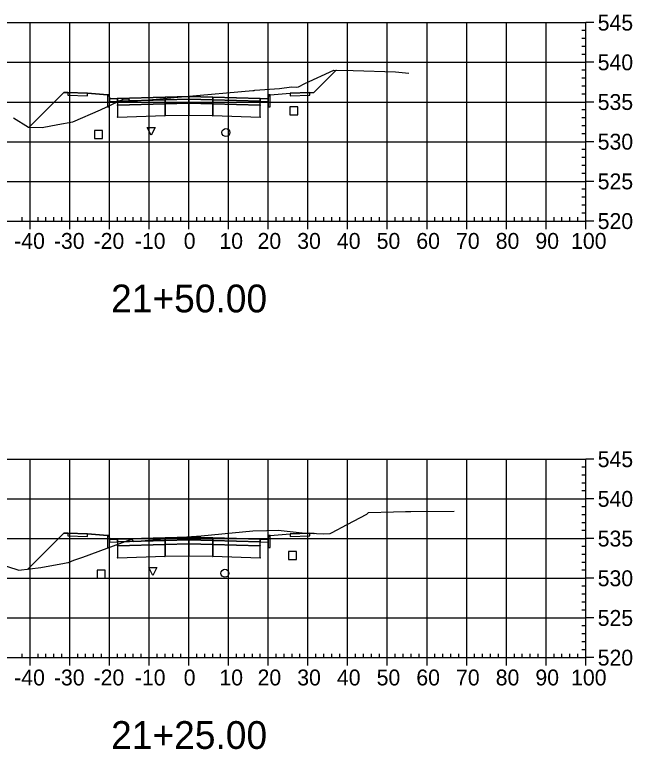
# Model space of a CAD drawing. Extents: x 704834 to 709892, y 372981 to 377533.
# Drawn here: x 707536 to 707691.6, y 376727.7 to 376912.8 of the extents above; entities that cross this region are included whole.
import ezdxf

# ---------------------------------------------------------------- set-up
doc = ezdxf.new("R2010")
doc.units = 0
for name, color, linetype in [('1', 7, 'Continuous'), ('10', 7, 'Continuous'), ('13', 7, 'Continuous'), ('14', 7, 'Continuous'), ('4', 7, 'Continuous'), ('57', 7, 'Continuous'), ('Default_Xsect', 7, 'Continuous'), ('Existing', 7, 'Continuous')]:
    doc.layers.add(name, color=color, linetype=linetype)

msp = doc.modelspace()

# ---------------------------------------------------------------- linework, layer by layer
for points in [[(707611.41, 376893.18), (707617.05, 376898.81)], [(707548.41, 376893.18), (707539.7, 376884.46)], [(707549.41, 376893.22), (707548.41, 376893.18)], [(707559.41, 376892.62), (707554.41, 376893.02)], [(707600.41, 376892.62), (707605.41, 376893.02)], [(707610.41, 376893.22), (707611.41, 376893.18)], [(707548.41, 376782.15), (707539.38, 376773.12)], [(707549.41, 376782.19), (707548.41, 376782.15)], [(707559.41, 376781.59), (707554.41, 376781.99)], [(707600.41, 376781.59), (707605.41, 376781.99)], [(707610.41, 376782.19), (707611.41, 376782.15)], [(707611.41, 376782.15), (707611.45, 376782.12)]]:
    msp.add_lwpolyline(points)
for points in [[(707554.41, 376893.02), (707549.41, 376893.22), (707549.41, 376892.55), (707554.41, 376892.35)], [(707559.91, 376891.62), (707559.83, 376892.62), (707559.41, 376892.62), (707559.41, 376889.62), (707559.91, 376889.62)], [(707573.91, 376892.06), (707561.91, 376891.7), (707561.91, 376891.03), (707573.91, 376891.39)], [(707579.91, 376892.18), (707573.91, 376892.06), (707573.91, 376891.39), (707579.91, 376891.51)], [(707579.91, 376891.51), (707585.91, 376891.39), (707585.91, 376892.06), (707579.91, 376892.18)], [(707585.91, 376891.39), (707597.91, 376891.03), (707597.91, 376891.7), (707585.91, 376892.06)], [(707599.91, 376889.62), (707600.41, 376889.62), (707600.41, 376892.62), (707600, 376892.62), (707599.91, 376891.62)], [(707605.41, 376892.35), (707610.41, 376892.55), (707610.41, 376893.22), (707605.41, 376893.02)], [(707561.91, 376891.7), (707559.91, 376891.62), (707559.91, 376890.95), (707561.91, 376891.03)], [(707561.86, 376889.98), (707561.96, 376889.98), (707561.96, 376890.08), (707561.86, 376890.08)], [(707573.91, 376891.39), (707561.91, 376891.03), (707561.91, 376890.03), (707573.91, 376890.39)], [(707573.91, 376890.39), (707561.91, 376890.03), (707561.91, 376887.03), (707573.91, 376887.39)], [(707573.86, 376891.34), (707573.96, 376891.34), (707573.96, 376891.44), (707573.86, 376891.44)], [(707573.86, 376890.34), (707573.96, 376890.34), (707573.96, 376890.44), (707573.86, 376890.44)], [(707579.91, 376891.51), (707573.91, 376891.39), (707573.91, 376890.39), (707579.91, 376890.51)], [(707579.91, 376890.51), (707573.91, 376890.39), (707573.91, 376887.39), (707579.91, 376887.51)], [(707579.86, 376891.46), (707579.96, 376891.46), (707579.96, 376891.56), (707579.86, 376891.56)], [(707579.86, 376890.46), (707579.96, 376890.46), (707579.96, 376890.56), (707579.86, 376890.56)], [(707579.91, 376890.51), (707585.91, 376890.39), (707585.91, 376891.39), (707579.91, 376891.51)], [(707579.91, 376887.51), (707585.91, 376887.39), (707585.91, 376890.39), (707579.91, 376890.51)], [(707585.86, 376891.34), (707585.96, 376891.34), (707585.96, 376891.44), (707585.86, 376891.44)], [(707585.86, 376890.34), (707585.96, 376890.34), (707585.96, 376890.44), (707585.86, 376890.44)], [(707585.91, 376890.39), (707597.91, 376890.03), (707597.91, 376891.03), (707585.91, 376891.39)], [(707585.91, 376887.39), (707597.91, 376887.03), (707597.91, 376890.03), (707585.91, 376890.39)], [(707597.86, 376889.98), (707597.96, 376889.98), (707597.96, 376890.08), (707597.86, 376890.08)], [(707597.91, 376891.03), (707599.91, 376890.95), (707599.91, 376891.62), (707597.91, 376891.7)], [(707561.86, 376886.98), (707561.96, 376886.98), (707561.96, 376887.08), (707561.86, 376887.08)], [(707573.86, 376887.34), (707573.96, 376887.34), (707573.96, 376887.44), (707573.86, 376887.44)], [(707579.86, 376887.46), (707579.96, 376887.46), (707579.96, 376887.56), (707579.86, 376887.56)], [(707585.86, 376887.34), (707585.96, 376887.34), (707585.96, 376887.44), (707585.86, 376887.44)], [(707597.86, 376886.98), (707597.96, 376886.98), (707597.96, 376887.08), (707597.86, 376887.08)], [(707554.41, 376781.99), (707549.41, 376782.19), (707549.41, 376781.53), (707554.41, 376781.33)], [(707559.91, 376780.59), (707559.83, 376781.59), (707559.41, 376781.59), (707559.41, 376778.59), (707559.91, 376778.59)], [(707573.91, 376781.03), (707561.91, 376780.67), (707561.91, 376780.01), (707573.91, 376780.37)], [(707579.91, 376781.15), (707573.91, 376781.03), (707573.91, 376780.37), (707579.91, 376780.49)], [(707579.91, 376780.49), (707585.91, 376780.37), (707585.91, 376781.03), (707579.91, 376781.15)], [(707585.91, 376780.37), (707597.91, 376780.01), (707597.91, 376780.67), (707585.91, 376781.03)], [(707599.91, 376778.59), (707600.41, 376778.59), (707600.41, 376781.59), (707600, 376781.59), (707599.91, 376780.59)], [(707605.41, 376781.33), (707610.41, 376781.53), (707610.41, 376782.19), (707605.41, 376781.99)], [(707561.91, 376780.67), (707559.91, 376780.59), (707559.91, 376779.93), (707561.91, 376780.01)], [(707561.86, 376778.96), (707561.96, 376778.96), (707561.96, 376779.06), (707561.86, 376779.06)], [(707573.91, 376780.37), (707561.91, 376780.01), (707561.91, 376779.01), (707573.91, 376779.37)], [(707573.91, 376779.37), (707561.91, 376779.01), (707561.91, 376776.01), (707573.91, 376776.37)], [(707573.86, 376780.32), (707573.96, 376780.32), (707573.96, 376780.42), (707573.86, 376780.42)], [(707573.86, 376779.32), (707573.96, 376779.32), (707573.96, 376779.42), (707573.86, 376779.42)], [(707579.91, 376780.49), (707573.91, 376780.37), (707573.91, 376779.37), (707579.91, 376779.49)], [(707579.91, 376779.49), (707573.91, 376779.37), (707573.91, 376776.37), (707579.91, 376776.49)], [(707579.86, 376780.44), (707579.96, 376780.44), (707579.96, 376780.54), (707579.86, 376780.54)], [(707579.86, 376779.44), (707579.96, 376779.44), (707579.96, 376779.54), (707579.86, 376779.54)], [(707579.91, 376779.49), (707585.91, 376779.37), (707585.91, 376780.37), (707579.91, 376780.49)], [(707579.91, 376776.49), (707585.91, 376776.37), (707585.91, 376779.37), (707579.91, 376779.49)], [(707585.86, 376780.32), (707585.96, 376780.32), (707585.96, 376780.42), (707585.86, 376780.42)], [(707585.86, 376779.32), (707585.96, 376779.32), (707585.96, 376779.42), (707585.86, 376779.42)], [(707585.91, 376779.37), (707597.91, 376779.01), (707597.91, 376780.01), (707585.91, 376780.37)], [(707585.91, 376776.37), (707597.91, 376776.01), (707597.91, 376779.01), (707585.91, 376779.37)], [(707597.86, 376778.96), (707597.96, 376778.96), (707597.96, 376779.06), (707597.86, 376779.06)], [(707597.91, 376780.01), (707599.91, 376779.93), (707599.91, 376780.59), (707597.91, 376780.67)], [(707561.86, 376775.96), (707561.96, 376775.96), (707561.96, 376776.06), (707561.86, 376776.06)], [(707573.86, 376776.32), (707573.96, 376776.32), (707573.96, 376776.42), (707573.86, 376776.42)], [(707579.86, 376776.44), (707579.96, 376776.44), (707579.96, 376776.54), (707579.86, 376776.54)], [(707585.86, 376776.32), (707585.96, 376776.32), (707585.96, 376776.42), (707585.86, 376776.42)], [(707597.86, 376775.96), (707597.96, 376775.96), (707597.96, 376776.06), (707597.86, 376776.06)]]:
    msp.add_lwpolyline(points, close=True)
at = {"layer": '1'}
for points in [[(707570.44, 376882.44), (707569.44, 376884.44), (707571.44, 376884.44)], [(707570.82, 376771.53), (707569.82, 376773.53), (707571.82, 376773.53)]]:
    msp.add_lwpolyline(points, close=True, dxfattribs=at)
at = {"layer": '10'}
for points in [[(707556.18, 376881.61), (707558.18, 376881.61), (707558.18, 376883.61), (707556.18, 376883.61)], [(707556.85, 376770.87), (707558.85, 376770.87), (707558.85, 376772.87), (707556.85, 376772.87)]]:
    msp.add_lwpolyline(points, close=True, dxfattribs=at)
at = {"layer": '13'}
for centre in [(707589.24, 376883.13), (707589, 376772.09)]:
    msp.add_circle(centre, 1, dxfattribs=at)
at = {"layer": '14'}
for points in [[(707617.05, 376898.81), (707617.05, 376898.86), (707617.05, 376898.81), (707617, 376898.81), (707617.05, 376898.81), (707617.05, 376898.76), (707617.05, 376898.81), (707617.1, 376898.81)], [(707579.91, 376892.18), (707579.91, 376892.23), (707579.91, 376892.18), (707579.86, 376892.18), (707579.91, 376892.18), (707579.91, 376892.13), (707579.91, 376892.18), (707579.96, 376892.18)], [(707561.91, 376891.7), (707561.91, 376891.75), (707561.91, 376891.7), (707561.86, 376891.7), (707561.91, 376891.7), (707561.91, 376891.65), (707561.91, 376891.7), (707561.96, 376891.7)], [(707597.91, 376891.7), (707597.91, 376891.75), (707597.91, 376891.7), (707597.86, 376891.7), (707597.91, 376891.7), (707597.91, 376891.65), (707597.91, 376891.7), (707597.96, 376891.7)], [(707539.7, 376884.46), (707539.7, 376884.51), (707539.7, 376884.46), (707539.65, 376884.46), (707539.7, 376884.46), (707539.7, 376884.41), (707539.7, 376884.46), (707539.75, 376884.46)], [(707579.91, 376781.15), (707579.91, 376781.2), (707579.91, 376781.15), (707579.86, 376781.15), (707579.91, 376781.15), (707579.91, 376781.1), (707579.91, 376781.15), (707579.96, 376781.15)], [(707611.45, 376782.12), (707611.45, 376782.17), (707611.45, 376782.12), (707611.4, 376782.12), (707611.45, 376782.12), (707611.45, 376782.07), (707611.45, 376782.12), (707611.5, 376782.12)], [(707611.45, 376782.12), (707611.45, 376782.17), (707611.45, 376782.12), (707611.4, 376782.12), (707611.45, 376782.12), (707611.45, 376782.07), (707611.45, 376782.12), (707611.5, 376782.12)], [(707561.91, 376780.67), (707561.91, 376780.72), (707561.91, 376780.67), (707561.86, 376780.67), (707561.91, 376780.67), (707561.91, 376780.62), (707561.91, 376780.67), (707561.96, 376780.67)], [(707597.91, 376780.67), (707597.91, 376780.72), (707597.91, 376780.67), (707597.86, 376780.67), (707597.91, 376780.67), (707597.91, 376780.62), (707597.91, 376780.67), (707597.96, 376780.67)], [(707539.38, 376773.12), (707539.38, 376773.17), (707539.38, 376773.12), (707539.33, 376773.12), (707539.38, 376773.12), (707539.38, 376773.07), (707539.38, 376773.12), (707539.43, 376773.12)]]:
    msp.add_lwpolyline(points, dxfattribs=at)
at = {"layer": '4'}
for points in [[(707605.36, 376887.59), (707607.36, 376887.59), (707607.36, 376889.59), (707605.36, 376889.59)], [(707605.01, 376775.57), (707607.01, 376775.57), (707607.01, 376777.57), (707605.01, 376777.57)]]:
    msp.add_lwpolyline(points, close=True, dxfattribs=at)
at = {"layer": '57'}
for p, q in [((707479.91, 376910.82), (707679.91, 376910.82)), ((707539.91, 376860.82), (707539.91, 376910.82)), ((707549.91, 376860.82), (707549.91, 376910.82)), ((707559.91, 376860.82), (707559.91, 376910.82)), ((707569.91, 376860.82), (707569.91, 376910.82)), ((707579.91, 376860.82), (707579.91, 376910.82)), ((707589.91, 376860.82), (707589.91, 376910.82)), ((707599.91, 376860.82), (707599.91, 376910.82)), ((707609.91, 376860.82), (707609.91, 376910.82)), ((707619.91, 376860.82), (707619.91, 376910.82)), ((707629.91, 376860.82), (707629.91, 376910.82)), ((707639.91, 376860.82), (707639.91, 376910.82)), ((707649.91, 376860.82), (707649.91, 376910.82)), ((707659.91, 376860.82), (707659.91, 376910.82)), ((707669.91, 376860.82), (707669.91, 376910.82)), ((707679.91, 376860.82), (707679.91, 376910.82)), ((707679.91, 376860.82), (707679.91, 376910.82)), ((707681.91, 376910.82), (707679.91, 376910.82)), ((707679.91, 376908.82), (707678.91, 376908.82)), ((707679.91, 376906.82), (707678.91, 376906.82)), ((707679.91, 376904.82), (707678.91, 376904.82)), ((707679.91, 376902.82), (707678.91, 376902.82)), ((707479.91, 376900.82), (707679.91, 376900.82)), ((707681.91, 376900.82), (707679.91, 376900.82)), ((707679.91, 376898.82), (707678.91, 376898.82)), ((707679.91, 376896.82), (707678.91, 376896.82)), ((707679.91, 376894.82), (707678.91, 376894.82)), ((707679.91, 376892.82), (707678.91, 376892.82)), ((707479.91, 376890.82), (707679.91, 376890.82)), ((707681.91, 376890.82), (707679.91, 376890.82)), ((707679.91, 376888.82), (707678.91, 376888.82)), ((707679.91, 376886.82), (707678.91, 376886.82)), ((707679.91, 376884.82), (707678.91, 376884.82)), ((707679.91, 376882.82), (707678.91, 376882.82)), ((707479.91, 376880.82), (707679.91, 376880.82)), ((707681.91, 376880.82), (707679.91, 376880.82)), ((707679.91, 376878.82), (707678.91, 376878.82)), ((707679.91, 376876.82), (707678.91, 376876.82)), ((707679.91, 376874.82), (707678.91, 376874.82)), ((707679.91, 376872.82), (707678.91, 376872.82)), ((707479.91, 376870.82), (707679.91, 376870.82)), ((707681.91, 376870.82), (707679.91, 376870.82)), ((707679.91, 376868.82), (707678.91, 376868.82)), ((707679.91, 376866.82), (707678.91, 376866.82)), ((707679.91, 376864.82), (707678.91, 376864.82)), ((707679.91, 376862.82), (707678.91, 376862.82)), ((707479.91, 376860.82), (707679.91, 376860.82)), ((707479.91, 376860.82), (707679.91, 376860.82)), ((707537.91, 376860.82), (707537.91, 376861.82)), ((707539.91, 376858.82), (707539.91, 376860.82)), ((707541.91, 376860.82), (707541.91, 376861.82)), ((707543.91, 376860.82), (707543.91, 376861.82)), ((707545.91, 376860.82), (707545.91, 376861.82)), ((707547.91, 376860.82), (707547.91, 376861.82)), ((707549.91, 376858.82), (707549.91, 376860.82)), ((707551.91, 376860.82), (707551.91, 376861.82)), ((707553.91, 376860.82), (707553.91, 376861.82)), ((707555.91, 376860.82), (707555.91, 376861.82)), ((707557.91, 376860.82), (707557.91, 376861.82)), ((707559.91, 376858.82), (707559.91, 376860.82)), ((707561.91, 376860.82), (707561.91, 376861.82)), ((707563.91, 376860.82), (707563.91, 376861.82)), ((707565.91, 376860.82), (707565.91, 376861.82)), ((707567.91, 376860.82), (707567.91, 376861.82)), ((707569.91, 376858.82), (707569.91, 376860.82)), ((707571.91, 376860.82), (707571.91, 376861.82)), ((707573.91, 376860.82), (707573.91, 376861.82)), ((707575.91, 376860.82), (707575.91, 376861.82)), ((707577.91, 376860.82), (707577.91, 376861.82)), ((707579.91, 376858.82), (707579.91, 376860.82)), ((707581.91, 376860.82), (707581.91, 376861.82)), ((707583.91, 376860.82), (707583.91, 376861.82)), ((707585.91, 376860.82), (707585.91, 376861.82)), ((707587.91, 376860.82), (707587.91, 376861.82)), ((707589.91, 376858.82), (707589.91, 376860.82)), ((707591.91, 376860.82), (707591.91, 376861.82)), ((707593.91, 376860.82), (707593.91, 376861.82)), ((707595.91, 376860.82), (707595.91, 376861.82)), ((707597.91, 376860.82), (707597.91, 376861.82)), ((707599.91, 376858.82), (707599.91, 376860.82)), ((707601.91, 376860.82), (707601.91, 376861.82)), ((707603.91, 376860.82), (707603.91, 376861.82)), ((707605.91, 376860.82), (707605.91, 376861.82)), ((707607.91, 376860.82), (707607.91, 376861.82)), ((707609.91, 376858.82), (707609.91, 376860.82)), ((707611.91, 376860.82), (707611.91, 376861.82)), ((707613.91, 376860.82), (707613.91, 376861.82)), ((707615.91, 376860.82), (707615.91, 376861.82)), ((707617.91, 376860.82), (707617.91, 376861.82)), ((707619.91, 376858.82), (707619.91, 376860.82)), ((707621.91, 376860.82), (707621.91, 376861.82)), ((707623.91, 376860.82), (707623.91, 376861.82)), ((707625.91, 376860.82), (707625.91, 376861.82)), ((707627.91, 376860.82), (707627.91, 376861.82)), ((707629.91, 376858.82), (707629.91, 376860.82)), ((707631.91, 376860.82), (707631.91, 376861.82)), ((707633.91, 376860.82), (707633.91, 376861.82)), ((707635.91, 376860.82), (707635.91, 376861.82)), ((707637.91, 376860.82), (707637.91, 376861.82)), ((707639.91, 376858.82), (707639.91, 376860.82)), ((707641.91, 376860.82), (707641.91, 376861.82)), ((707643.91, 376860.82), (707643.91, 376861.82)), ((707645.91, 376860.82), (707645.91, 376861.82)), ((707647.91, 376860.82), (707647.91, 376861.82)), ((707649.91, 376858.82), (707649.91, 376860.82)), ((707651.91, 376860.82), (707651.91, 376861.82)), ((707653.91, 376860.82), (707653.91, 376861.82)), ((707655.91, 376860.82), (707655.91, 376861.82)), ((707657.91, 376860.82), (707657.91, 376861.82)), ((707659.91, 376858.82), (707659.91, 376860.82)), ((707661.91, 376860.82), (707661.91, 376861.82)), ((707663.91, 376860.82), (707663.91, 376861.82)), ((707665.91, 376860.82), (707665.91, 376861.82)), ((707667.91, 376860.82), (707667.91, 376861.82)), ((707669.91, 376858.82), (707669.91, 376860.82)), ((707671.91, 376860.82), (707671.91, 376861.82)), ((707673.91, 376860.82), (707673.91, 376861.82)), ((707675.91, 376860.82), (707675.91, 376861.82)), ((707677.91, 376860.82), (707677.91, 376861.82)), ((707679.91, 376858.82), (707679.91, 376860.82)), ((707681.91, 376860.82), (707679.91, 376860.82)), ((707479.91, 376800.82), (707679.91, 376800.82)), ((707539.91, 376750.82), (707539.91, 376800.82)), ((707549.91, 376750.82), (707549.91, 376800.82)), ((707559.91, 376750.82), (707559.91, 376800.82)), ((707569.91, 376750.82), (707569.91, 376800.82)), ((707579.91, 376750.82), (707579.91, 376800.82)), ((707589.91, 376750.82), (707589.91, 376800.82)), ((707599.91, 376750.82), (707599.91, 376800.82)), ((707609.91, 376750.82), (707609.91, 376800.82)), ((707619.91, 376750.82), (707619.91, 376800.82)), ((707629.91, 376750.82), (707629.91, 376800.82)), ((707639.91, 376750.82), (707639.91, 376800.82)), ((707649.91, 376750.82), (707649.91, 376800.82)), ((707659.91, 376750.82), (707659.91, 376800.82)), ((707669.91, 376750.82), (707669.91, 376800.82)), ((707679.91, 376750.82), (707679.91, 376800.82)), ((707679.91, 376750.82), (707679.91, 376800.82)), ((707681.91, 376800.82), (707679.91, 376800.82)), ((707679.91, 376798.82), (707678.91, 376798.82)), ((707679.91, 376796.82), (707678.91, 376796.82)), ((707679.91, 376794.82), (707678.91, 376794.82)), ((707679.91, 376792.82), (707678.91, 376792.82)), ((707479.91, 376790.82), (707679.91, 376790.82)), ((707681.91, 376790.82), (707679.91, 376790.82)), ((707679.91, 376788.82), (707678.91, 376788.82)), ((707679.91, 376786.82), (707678.91, 376786.82)), ((707679.91, 376784.82), (707678.91, 376784.82)), ((707679.91, 376782.82), (707678.91, 376782.82)), ((707479.91, 376780.82), (707679.91, 376780.82)), ((707681.91, 376780.82), (707679.91, 376780.82)), ((707679.91, 376778.82), (707678.91, 376778.82)), ((707679.91, 376776.82), (707678.91, 376776.82)), ((707679.91, 376774.82), (707678.91, 376774.82)), ((707679.91, 376772.82), (707678.91, 376772.82)), ((707479.91, 376770.82), (707679.91, 376770.82)), ((707681.91, 376770.82), (707679.91, 376770.82)), ((707679.91, 376768.82), (707678.91, 376768.82)), ((707679.91, 376766.82), (707678.91, 376766.82)), ((707679.91, 376764.82), (707678.91, 376764.82)), ((707679.91, 376762.82), (707678.91, 376762.82)), ((707479.91, 376760.82), (707679.91, 376760.82)), ((707681.91, 376760.82), (707679.91, 376760.82)), ((707679.91, 376758.82), (707678.91, 376758.82)), ((707679.91, 376756.82), (707678.91, 376756.82)), ((707679.91, 376754.82), (707678.91, 376754.82)), ((707537.91, 376750.82), (707537.91, 376751.82)), ((707541.91, 376750.82), (707541.91, 376751.82)), ((707543.91, 376750.82), (707543.91, 376751.82)), ((707545.91, 376750.82), (707545.91, 376751.82)), ((707547.91, 376750.82), (707547.91, 376751.82)), ((707551.91, 376750.82), (707551.91, 376751.82)), ((707553.91, 376750.82), (707553.91, 376751.82)), ((707555.91, 376750.82), (707555.91, 376751.82)), ((707557.91, 376750.82), (707557.91, 376751.82)), ((707561.91, 376750.82), (707561.91, 376751.82)), ((707563.91, 376750.82), (707563.91, 376751.82)), ((707565.91, 376750.82), (707565.91, 376751.82)), ((707567.91, 376750.82), (707567.91, 376751.82)), ((707571.91, 376750.82), (707571.91, 376751.82)), ((707573.91, 376750.82), (707573.91, 376751.82)), ((707575.91, 376750.82), (707575.91, 376751.82)), ((707577.91, 376750.82), (707577.91, 376751.82)), ((707581.91, 376750.82), (707581.91, 376751.82)), ((707583.91, 376750.82), (707583.91, 376751.82)), ((707585.91, 376750.82), (707585.91, 376751.82)), ((707587.91, 376750.82), (707587.91, 376751.82)), ((707591.91, 376750.82), (707591.91, 376751.82)), ((707593.91, 376750.82), (707593.91, 376751.82)), ((707595.91, 376750.82), (707595.91, 376751.82)), ((707597.91, 376750.82), (707597.91, 376751.82)), ((707601.91, 376750.82), (707601.91, 376751.82)), ((707603.91, 376750.82), (707603.91, 376751.82)), ((707605.91, 376750.82), (707605.91, 376751.82)), ((707607.91, 376750.82), (707607.91, 376751.82)), ((707611.91, 376750.82), (707611.91, 376751.82)), ((707613.91, 376750.82), (707613.91, 376751.82)), ((707615.91, 376750.82), (707615.91, 376751.82)), ((707617.91, 376750.82), (707617.91, 376751.82)), ((707621.91, 376750.82), (707621.91, 376751.82)), ((707623.91, 376750.82), (707623.91, 376751.82)), ((707625.91, 376750.82), (707625.91, 376751.82)), ((707627.91, 376750.82), (707627.91, 376751.82)), ((707631.91, 376750.82), (707631.91, 376751.82)), ((707633.91, 376750.82), (707633.91, 376751.82)), ((707635.91, 376750.82), (707635.91, 376751.82)), ((707637.91, 376750.82), (707637.91, 376751.82)), ((707641.91, 376750.82), (707641.91, 376751.82)), ((707643.91, 376750.82), (707643.91, 376751.82)), ((707645.91, 376750.82), (707645.91, 376751.82)), ((707647.91, 376750.82), (707647.91, 376751.82)), ((707651.91, 376750.82), (707651.91, 376751.82)), ((707653.91, 376750.82), (707653.91, 376751.82)), ((707655.91, 376750.82), (707655.91, 376751.82)), ((707657.91, 376750.82), (707657.91, 376751.82)), ((707661.91, 376750.82), (707661.91, 376751.82)), ((707663.91, 376750.82), (707663.91, 376751.82)), ((707665.91, 376750.82), (707665.91, 376751.82)), ((707667.91, 376750.82), (707667.91, 376751.82)), ((707671.91, 376750.82), (707671.91, 376751.82)), ((707673.91, 376750.82), (707673.91, 376751.82)), ((707675.91, 376750.82), (707675.91, 376751.82)), ((707677.91, 376750.82), (707677.91, 376751.82)), ((707679.91, 376752.82), (707678.91, 376752.82)), ((707479.91, 376750.82), (707679.91, 376750.82)), ((707479.91, 376750.82), (707679.91, 376750.82)), ((707539.91, 376748.82), (707539.91, 376750.82)), ((707549.91, 376748.82), (707549.91, 376750.82)), ((707559.91, 376748.82), (707559.91, 376750.82)), ((707569.91, 376748.82), (707569.91, 376750.82)), ((707579.91, 376748.82), (707579.91, 376750.82)), ((707589.91, 376748.82), (707589.91, 376750.82)), ((707599.91, 376748.82), (707599.91, 376750.82)), ((707609.91, 376748.82), (707609.91, 376750.82)), ((707619.91, 376748.82), (707619.91, 376750.82)), ((707629.91, 376748.82), (707629.91, 376750.82)), ((707639.91, 376748.82), (707639.91, 376750.82)), ((707649.91, 376748.82), (707649.91, 376750.82)), ((707659.91, 376748.82), (707659.91, 376750.82)), ((707669.91, 376748.82), (707669.91, 376750.82)), ((707679.91, 376748.82), (707679.91, 376750.82)), ((707681.91, 376750.82), (707679.91, 376750.82))]:
    msp.add_line(p, q, dxfattribs=at)
at = {"layer": 'Default_Xsect'}
for points in [[(707539.7, 376884.46), (707548.41, 376893.18), (707549.41, 376893.22), (707554.41, 376893.02), (707559.41, 376892.62), (707559.83, 376892.62), (707559.91, 376891.62), (707561.91, 376891.7), (707573.91, 376892.06), (707579.91, 376892.18), (707585.91, 376892.06), (707597.91, 376891.7), (707599.91, 376891.62), (707600, 376892.62), (707600.41, 376892.62), (707605.41, 376893.02), (707610.41, 376893.22), (707611.41, 376893.18), (707617.05, 376898.81)], [(707539.38, 376773.12), (707548.41, 376782.15), (707549.41, 376782.19), (707554.41, 376781.99), (707559.41, 376781.59), (707559.83, 376781.59), (707559.91, 376780.59), (707561.91, 376780.67), (707573.91, 376781.03), (707579.91, 376781.15), (707585.91, 376781.03), (707597.91, 376780.67), (707599.91, 376780.59), (707600, 376781.59), (707600.41, 376781.59), (707605.41, 376781.99), (707610.41, 376782.19), (707611.41, 376782.15), (707611.45, 376782.12)]]:
    msp.add_lwpolyline(points, dxfattribs=at)
at = {"layer": 'Existing'}
for points in [[(707535.71, 376886.81), (707539.55, 376884.46), (707542.93, 376884.44), (707546.86, 376885.14), (707550.68, 376885.8), (707557.68, 376888.82), (707563.5, 376891.6), (707564.66, 376891.58), (707564.97, 376891.22), (707565.12, 376890.98), (707573.51, 376891.7), (707578.95, 376892.25), (707596.02, 376893.71), (707596.36, 376893.74), (707596.52, 376893.77), (707602.74, 376894.22), (707605.78, 376894.61), (707607.03, 376894.57), (707607.54, 376894.61), (707609.14, 376895.47), (707616.4, 376898.82), (707621.31, 376898.75), (707631.95, 376898.42), (707635.32, 376898.11)], [(707531.28, 376774.74), (707537.05, 376772.85), (707542.63, 376773.5), (707548.62, 376774.66), (707549.42, 376774.8), (707549.59, 376774.83), (707550.93, 376775.4), (707553.17, 376776.15), (707565.46, 376780.67), (707565.51, 376780.62), (707565.94, 376780.12), (707577.66, 376781.11), (707579.42, 376781.27), (707583.03, 376781.55), (707596.04, 376782.74), (707599.52, 376782.89), (707602.43, 376782.98), (707608.48, 376782.29), (707613.79, 376781.99), (707615.55, 376782.09), (707617.57, 376783.16), (707618.18, 376783.49), (707624.76, 376787.01), (707625.14, 376787.37), (707631.44, 376787.58), (707634.53, 376787.64), (707635.8, 376787.63), (707646.77, 376787.73)]]:
    msp.add_lwpolyline(points, dxfattribs=at)

# ---------------------------------------------------------------- texts
at = {"layer": '1'}
for s, p in [('21+50.00', (707560.32, 376837.82)), ('21+25.00', (707560.32, 376727.82))]:
    msp.add_text(s, height=7, dxfattribs=at).set_placement(p)
at = {"layer": '14'}
for p in [(707549.38, 376893.17), (707549.38, 376892.5), (707554.38, 376892.3), (707605.38, 376892.3), (707610.38, 376893.17), (707610.38, 376892.5), (707549.38, 376782.14), (707549.38, 376781.48), (707554.38, 376781.28), (707605.38, 376781.28), (707610.38, 376782.14), (707610.38, 376781.48)]:
    msp.add_text('+', height=0.1, dxfattribs=at).set_placement(p)
at = {"layer": '57'}
for s, p in [('545', (707682.91, 376908.82)), ('540', (707682.91, 376898.82)), ('535', (707682.91, 376888.82)), ('530', (707682.91, 376878.82)), ('525', (707682.91, 376868.82)), ('520', (707682.91, 376858.82)), ('-40', (707535.91, 376853.82)), ('-30', (707545.91, 376853.82)), ('-20', (707555.91, 376853.82)), ('-10', (707566.3, 376853.82)), ('0', (707578.62, 376853.82)), ('10', (707587.61, 376853.82)), ('20', (707597.22, 376853.82)), ('30', (707607.22, 376853.82)), ('40', (707617.22, 376853.82)), ('50', (707627.22, 376853.82)), ('60', (707637.22, 376853.82)), ('70', (707647.22, 376853.82)), ('80', (707657.22, 376853.82)), ('90', (707667.22, 376853.82)), ('100', (707676.21, 376853.82)), ('545', (707682.91, 376798.82)), ('540', (707682.91, 376788.82)), ('535', (707682.91, 376778.82)), ('530', (707682.91, 376768.82)), ('525', (707682.91, 376758.82)), ('520', (707682.91, 376748.82)), ('-40', (707535.91, 376743.82)), ('-30', (707545.91, 376743.82)), ('-20', (707555.91, 376743.82)), ('-10', (707566.3, 376743.82)), ('0', (707578.62, 376743.82)), ('10', (707587.61, 376743.82)), ('20', (707597.22, 376743.82)), ('30', (707607.22, 376743.82)), ('40', (707617.22, 376743.82)), ('50', (707627.22, 376743.82)), ('60', (707637.22, 376743.82)), ('70', (707647.22, 376743.82)), ('80', (707657.22, 376743.82)), ('90', (707667.22, 376743.82)), ('100', (707676.21, 376743.82))]:
    msp.add_text(s, height=4, dxfattribs=at).set_placement(p)

doc.saveas('drawing.dxf')
